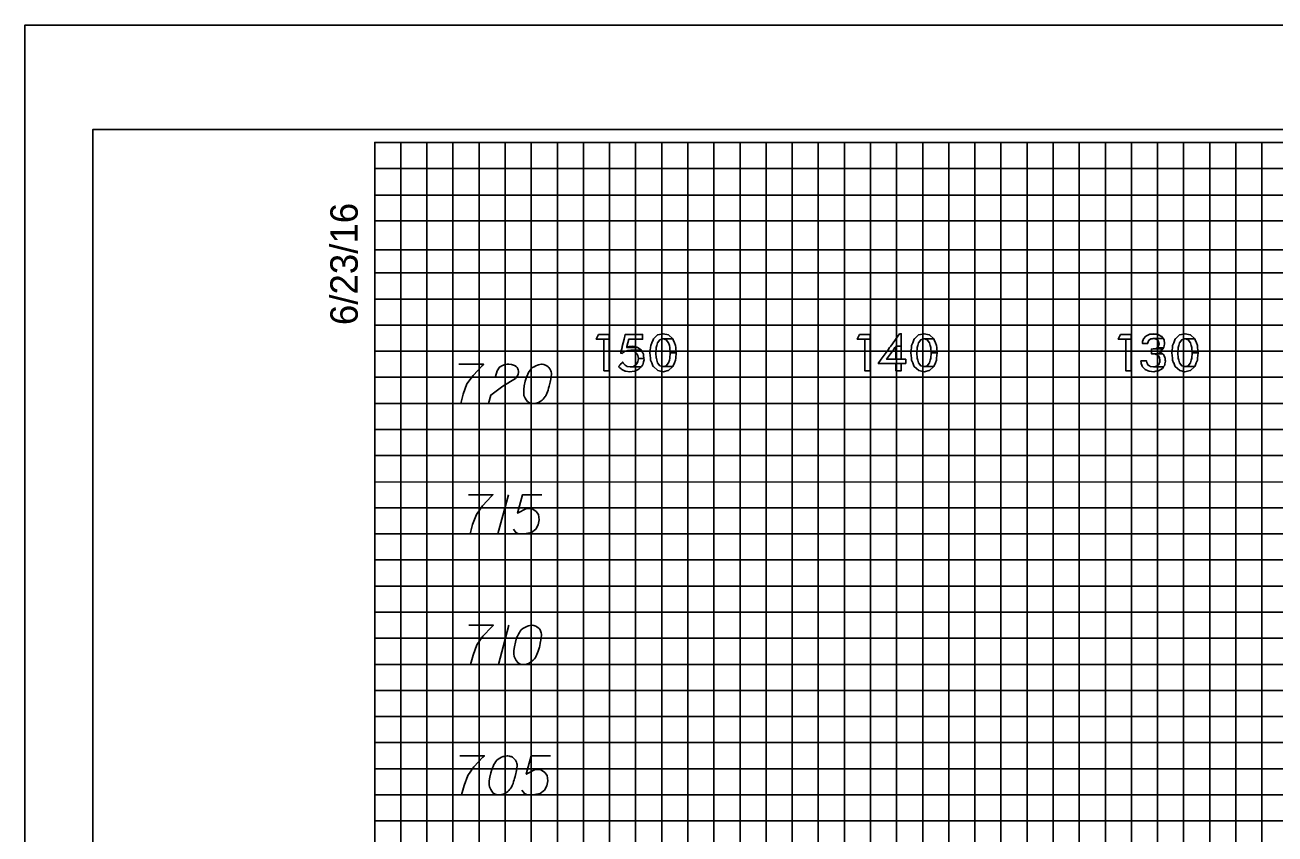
# Model space of a CAD drawing. Extents: x -13 to 323, y -5 to 1431.
# Drawn here: x -13.4 to 34.5, y 623.5 to 654.5 of the extents above; entities that cross this region are included whole.
import ezdxf

# ---------------------------------------------------------------- set-up
doc = ezdxf.new("R2010")
doc.units = 0
for name, color, linetype in [('Prop XS Elevation Labels', 7, 'Continuous'), ('Prop XS Offset Labels', 7, 'Continuous'), ('Sheet Cross Section CELL', 7, 'Continuous'), ('Sheet Cross Section Grid Major CELL', 7, 'Continuous'), ('Sheet Cross Section Grid Middle CELL', 7, 'Continuous'), ('Sheet Cross Section Grid Minor 1 CELL', 7, 'Continuous'), ('Sheet Cross Section Grid Minor 2 CELL', 7, 'Continuous'), ('Sheet Cutting Line CELL', 7, 'Continuous'), ('Sheet DOT Grid CELL', 7, 'Continuous'), ('Sheet Plot Border Inside CELL', 7, 'Continuous'), ('Sheet Plot Border Outside CELL', 7, 'Continuous')]:
    doc.layers.add(name, color=color, linetype=linetype)

msp = doc.modelspace()

# ---------------------------------------------------------------- linework, layer by layer
at = {"layer": 'Prop XS Elevation Labels'}
for p, q in [((5.124, 636.5), (4.723, 635)), ((5.142, 631.5), (4.74, 630))]:
    msp.add_line(p, q, dxfattribs=at)
for points in [[(3.228, 641.5), (4.173, 641.5), (4.114, 641.441), (3.772, 641.075), (3.535, 640.744), (3.394, 640.354), (3.299, 640)], [(4.634, 641.028), (4.693, 641.252), (4.787, 641.394), (4.894, 641.453), (5, 641.488), (5.083, 641.5), (5.142, 641.5), (5.248, 641.488), (5.319, 641.465), (5.354, 641.453), (5.425, 641.417), (5.461, 641.37), (5.484, 641.323), (5.496, 641.287), (5.508, 641.24), (5.508, 641.181), (5.496, 641.122), (5.484, 641.087), (5.461, 641.039), (5.425, 640.992), (5.39, 640.957), (4.906, 640.661), (4.445, 640.319), (4.362, 640), (5.437, 640)], [(6.417, 641.5), (6.394, 641.5), (6.323, 641.488), (6.276, 641.476), (6.24, 641.465), (6.181, 641.441), (6.11, 641.406), (6.051, 641.37), (5.992, 641.323), (5.957, 641.276), (5.921, 641.217), (5.886, 641.158), (5.85, 641.087), (5.827, 641.039), (5.803, 640.969), (5.768, 640.85), (5.732, 640.673), (5.709, 640.531), (5.709, 640.402), (5.721, 640.307), (5.768, 640.201), (5.803, 640.142), (5.862, 640.071), (5.933, 640.024), (5.968, 640.012), (6.039, 640), (6.098, 640), (6.193, 640.012), (6.276, 640.035), (6.335, 640.071), (6.417, 640.13), (6.453, 640.165), (6.5, 640.213), (6.535, 640.26), (6.559, 640.295), (6.583, 640.354), (6.594, 640.378), (6.618, 640.437), (6.642, 640.508), (6.665, 640.579), (6.677, 640.626), (6.689, 640.661), (6.701, 640.709), (6.724, 640.815), (6.736, 640.874), (6.748, 640.933), (6.76, 641.016), (6.772, 641.122), (6.772, 641.158), (6.76, 641.205), (6.748, 641.252), (6.713, 641.323), (6.677, 641.37), (6.642, 641.406), (6.594, 641.441), (6.547, 641.465), (6.512, 641.476), (6.476, 641.488), (6.417, 641.5)], [(3.589, 636.5), (4.533, 636.5), (4.474, 636.441), (4.132, 636.075), (3.896, 635.744), (3.754, 635.354), (3.659, 635)], [(6.411, 636.5), (5.667, 636.5), (5.478, 635.791), (5.821, 635.969), (6.022, 635.969), (6.187, 635.862), (6.282, 635.744), (6.305, 635.543), (6.27, 635.342), (6.175, 635.177), (6.01, 635.047), (5.726, 635), (5.514, 635), (5.408, 635.047), (5.313, 635.177)], [(3.606, 631.5), (4.551, 631.5), (4.492, 631.441), (4.149, 631.075), (3.913, 630.744), (3.772, 630.354), (3.677, 630)], [(6.039, 631.5), (6.016, 631.5), (5.945, 631.488), (5.898, 631.476), (5.862, 631.465), (5.803, 631.441), (5.732, 631.406), (5.673, 631.37), (5.614, 631.323), (5.579, 631.276), (5.543, 631.217), (5.508, 631.158), (5.472, 631.087), (5.449, 631.039), (5.425, 630.969), (5.39, 630.85), (5.354, 630.673), (5.331, 630.531), (5.331, 630.402), (5.343, 630.307), (5.39, 630.201), (5.425, 630.142), (5.484, 630.071), (5.555, 630.024), (5.591, 630.012), (5.661, 630), (5.72, 630), (5.815, 630.012), (5.898, 630.035), (5.957, 630.071), (6.039, 630.13), (6.075, 630.165), (6.122, 630.213), (6.157, 630.26), (6.181, 630.295), (6.205, 630.354), (6.217, 630.378), (6.24, 630.437), (6.264, 630.508), (6.287, 630.579), (6.299, 630.626), (6.311, 630.661), (6.323, 630.709), (6.347, 630.815), (6.358, 630.874), (6.37, 630.933), (6.382, 631.016), (6.394, 631.122), (6.394, 631.158), (6.382, 631.205), (6.37, 631.252), (6.335, 631.323), (6.299, 631.37), (6.264, 631.406), (6.217, 631.441), (6.169, 631.465), (6.134, 631.476), (6.098, 631.488), (6.039, 631.5)], [(3.258, 626.5), (4.203, 626.5), (4.144, 626.441), (3.801, 626.075), (3.565, 625.744), (3.423, 625.354), (3.329, 625)], [(5.1, 626.5), (5.077, 626.5), (5.006, 626.488), (4.959, 626.476), (4.923, 626.465), (4.864, 626.441), (4.793, 626.406), (4.734, 626.37), (4.675, 626.323), (4.64, 626.276), (4.604, 626.217), (4.569, 626.158), (4.534, 626.087), (4.51, 626.039), (4.486, 625.969), (4.451, 625.85), (4.415, 625.673), (4.392, 625.531), (4.392, 625.402), (4.404, 625.307), (4.451, 625.201), (4.486, 625.142), (4.545, 625.071), (4.616, 625.024), (4.652, 625.012), (4.723, 625), (4.781, 625), (4.876, 625.012), (4.959, 625.035), (5.018, 625.071), (5.1, 625.13), (5.136, 625.165), (5.183, 625.213), (5.219, 625.26), (5.242, 625.295), (5.266, 625.354), (5.278, 625.378), (5.301, 625.437), (5.325, 625.508), (5.349, 625.579), (5.36, 625.626), (5.372, 625.661), (5.384, 625.709), (5.408, 625.815), (5.419, 625.874), (5.431, 625.933), (5.443, 626.016), (5.455, 626.122), (5.455, 626.158), (5.443, 626.205), (5.431, 626.252), (5.396, 626.323), (5.36, 626.37), (5.325, 626.406), (5.278, 626.441), (5.23, 626.465), (5.195, 626.476), (5.16, 626.488), (5.1, 626.5)], [(6.742, 626.5), (5.998, 626.5), (5.809, 625.791), (6.152, 625.969), (6.352, 625.969), (6.518, 625.862), (6.612, 625.744), (6.636, 625.543), (6.6, 625.342), (6.506, 625.177), (6.341, 625.047), (6.057, 625), (5.845, 625), (5.738, 625.047), (5.644, 625.177)]]:
    msp.add_lwpolyline(points, dxfattribs=at)
at = {"layer": 'Prop XS Offset Labels'}
for points in [[(8.581, 642.641), (8.492, 642.459), (8.99, 642.459), (8.99, 642.641)], [(8.781, 642.459), (8.781, 641.25), (8.99, 641.25), (8.99, 642.459)], [(9.427, 641.94), (9.424, 641.928), (9.495, 641.928), (9.508, 641.94), (9.524, 641.954), (9.595, 641.997), (9.627, 642.007), (9.697, 642.029), (9.811, 642.035), (10.219, 642.035), (10.211, 642.05), (10.076, 642.145), (9.655, 642.145), (9.658, 642.158), (9.658, 642.158), (9.663, 642.178), (9.738, 642.456), (10.263, 642.456), (10.263, 642.641), (9.6, 642.641), (9.554, 642.456), (9.486, 642.178), (9.481, 642.158), (9.478, 642.145), (9.454, 642.05), (9.451, 642.035), (9.449, 642.029), (9.444, 642.007), (9.441, 641.997), (9.431, 641.954)], [(10.851, 641.255), (11.051, 641.214), (11.245, 641.255), (11.256, 641.257), (11.422, 641.409), (11.047, 641.409), (11.038, 641.411), (11.033, 641.413), (10.928, 641.442), (10.841, 641.555), (10.841, 641.556), (10.841, 641.556), (10.813, 641.657), (10.813, 641.659), (10.793, 641.732), (10.792, 641.736), (10.774, 641.939), (10.774, 641.941), (10.774, 641.943), (10.792, 642.145), (10.812, 642.222), (10.813, 642.224), (10.839, 642.322), (10.84, 642.325), (10.928, 642.44), (11.041, 642.469), (11.045, 642.47), (11.055, 642.473), (11.425, 642.473), (11.262, 642.622), (11.254, 642.624), (11.053, 642.668), (11.053, 642.668), (10.845, 642.624), (10.843, 642.622), (10.681, 642.473), (10.678, 642.47), (10.678, 642.469), (10.665, 642.44), (10.618, 642.325), (10.617, 642.322), (10.577, 642.224), (10.576, 642.222), (10.568, 642.145), (10.547, 641.943), (10.547, 641.941), (10.547, 641.939), (10.567, 641.736), (10.568, 641.732), (10.575, 641.659), (10.575, 641.657), (10.616, 641.556), (10.617, 641.555), (10.663, 641.442), (10.675, 641.413), (10.676, 641.411), (10.679, 641.409), (10.848, 641.257)], [(11.312, 642.145), (11.328, 641.943), (11.555, 641.943), (11.536, 642.145), (11.528, 642.222), (11.527, 642.224), (11.527, 642.224), (11.488, 642.322), (11.488, 642.322), (11.487, 642.325), (11.441, 642.44), (11.44, 642.44), (11.429, 642.469), (11.428, 642.47), (11.425, 642.473), (11.055, 642.473), (11.065, 642.47), (11.068, 642.469), (11.175, 642.44), (11.262, 642.325), (11.265, 642.322), (11.291, 642.224), (11.291, 642.222)], [(18.581, 642.641), (18.492, 642.459), (18.99, 642.459), (18.99, 642.641)], [(18.781, 642.459), (18.781, 641.25), (18.99, 641.25), (18.99, 642.459)], [(19.411, 641.693), (19.297, 641.534), (20.35, 641.534), (20.35, 641.693), (19.618, 641.693), (19.878, 642.059), (19.935, 642.139), (19.977, 642.199), (20.179, 642.199), (20.179, 642.668), (20.114, 642.668), (19.775, 642.199), (19.733, 642.139), (19.675, 642.059)], [(20.851, 641.255), (21.051, 641.214), (21.245, 641.255), (21.256, 641.257), (21.422, 641.409), (21.047, 641.409), (21.038, 641.411), (21.033, 641.413), (20.928, 641.442), (20.841, 641.555), (20.841, 641.556), (20.841, 641.556), (20.813, 641.657), (20.813, 641.659), (20.793, 641.732), (20.792, 641.736), (20.774, 641.939), (20.774, 641.941), (20.774, 641.943), (20.792, 642.145), (20.812, 642.222), (20.813, 642.224), (20.839, 642.322), (20.84, 642.325), (20.928, 642.44), (21.041, 642.469), (21.045, 642.47), (21.055, 642.473), (21.425, 642.473), (21.262, 642.622), (21.254, 642.624), (21.053, 642.668), (21.053, 642.668), (20.845, 642.624), (20.843, 642.622), (20.681, 642.473), (20.678, 642.47), (20.678, 642.469), (20.665, 642.44), (20.618, 642.325), (20.617, 642.322), (20.577, 642.224), (20.576, 642.222), (20.568, 642.145), (20.547, 641.943), (20.547, 641.941), (20.547, 641.939), (20.567, 641.736), (20.567, 641.732), (20.575, 641.659), (20.575, 641.657), (20.616, 641.556), (20.617, 641.555), (20.663, 641.442), (20.675, 641.413), (20.676, 641.411), (20.679, 641.409), (20.848, 641.257)], [(21.312, 642.145), (21.328, 641.943), (21.555, 641.943), (21.536, 642.145), (21.528, 642.222), (21.527, 642.224), (21.527, 642.224), (21.488, 642.322), (21.488, 642.322), (21.487, 642.325), (21.441, 642.44), (21.44, 642.44), (21.429, 642.469), (21.428, 642.47), (21.425, 642.473), (21.055, 642.473), (21.065, 642.47), (21.068, 642.469), (21.175, 642.44), (21.262, 642.325), (21.265, 642.322), (21.291, 642.224), (21.291, 642.222)], [(28.581, 642.641), (28.492, 642.459), (28.99, 642.459), (28.99, 642.641)], [(28.781, 642.459), (28.781, 641.25), (28.99, 641.25), (28.99, 642.459)], [(29.42, 642.315), (29.418, 642.297), (29.626, 642.297), (29.627, 642.315), (29.639, 642.365), (29.64, 642.372), (29.641, 642.373), (29.683, 642.433), (29.688, 642.436), (29.696, 642.44), (29.748, 642.47), (29.785, 642.476), (29.795, 642.478), (29.835, 642.485), (30.217, 642.485), (30.165, 642.561), (30.129, 642.582), (30.128, 642.582), (30.023, 642.644), (29.982, 642.65), (29.69, 642.65), (29.678, 642.644), (29.553, 642.582), (29.536, 642.561), (29.471, 642.485), (29.466, 642.478), (29.465, 642.476), (29.463, 642.47), (29.452, 642.44), (29.45, 642.436), (29.449, 642.433), (29.428, 642.373), (29.427, 642.372), (29.425, 642.365)], [(29.853, 642.668), (29.69, 642.65), (29.982, 642.65)], [(30.007, 642.155), (29.988, 642.131), (30.23, 642.131), (30.246, 642.155), (30.254, 642.201), (30.271, 642.289), (30.272, 642.295), (30.272, 642.297), (30.269, 642.315), (30.26, 642.365), (30.259, 642.372), (30.259, 642.373), (30.259, 642.373), (30.249, 642.433), (30.248, 642.436), (30.248, 642.44), (30.227, 642.47), (30.223, 642.476), (30.222, 642.478), (30.217, 642.485), (29.835, 642.485), (29.901, 642.478), (29.919, 642.476), (29.931, 642.47), (29.986, 642.44), (29.995, 642.436), (29.997, 642.433), (30.04, 642.373), (30.04, 642.372), (30.042, 642.365), (30.051, 642.315), (30.054, 642.297), (30.055, 642.295), (30.056, 642.289), (30.041, 642.201)], [(30.851, 641.255), (31.051, 641.214), (31.245, 641.255), (31.256, 641.257), (31.422, 641.409), (31.047, 641.409), (31.038, 641.411), (31.033, 641.413), (30.928, 641.442), (30.841, 641.555), (30.841, 641.556), (30.841, 641.556), (30.813, 641.657), (30.813, 641.659), (30.793, 641.732), (30.792, 641.736), (30.774, 641.939), (30.774, 641.941), (30.774, 641.943), (30.792, 642.145), (30.812, 642.222), (30.813, 642.224), (30.839, 642.322), (30.84, 642.325), (30.928, 642.44), (31.041, 642.469), (31.045, 642.47), (31.055, 642.473), (31.425, 642.473), (31.262, 642.622), (31.254, 642.624), (31.053, 642.668), (31.053, 642.668), (30.845, 642.624), (30.843, 642.622), (30.681, 642.473), (30.678, 642.47), (30.678, 642.469), (30.665, 642.44), (30.618, 642.325), (30.617, 642.322), (30.577, 642.224), (30.576, 642.222), (30.568, 642.145), (30.547, 641.943), (30.547, 641.941), (30.547, 641.939), (30.567, 641.736), (30.567, 641.732), (30.575, 641.659), (30.575, 641.657), (30.616, 641.556), (30.617, 641.555), (30.663, 641.442), (30.675, 641.413), (30.676, 641.411), (30.679, 641.409), (30.848, 641.257)], [(31.312, 642.145), (31.328, 641.943), (31.555, 641.943), (31.536, 642.145), (31.528, 642.222), (31.527, 642.224), (31.527, 642.224), (31.488, 642.322), (31.488, 642.322), (31.487, 642.325), (31.441, 642.44), (31.44, 642.44), (31.429, 642.469), (31.428, 642.47), (31.425, 642.473), (31.055, 642.473), (31.065, 642.47), (31.068, 642.469), (31.175, 642.44), (31.262, 642.325), (31.265, 642.322), (31.291, 642.224), (31.291, 642.222)], [(9.424, 641.928), (9.482, 641.916), (9.495, 641.928)], [(9.692, 642.158), (9.655, 642.145), (10.076, 642.145), (10.058, 642.158), (9.961, 642.178), (9.75, 642.178)], [(9.888, 642.192), (9.75, 642.178), (9.96, 642.178), (9.888, 642.192)], [(10.083, 641.841), (10.105, 641.721), (10.318, 641.721), (10.307, 641.841), (10.307, 641.841), (10.303, 641.881), (10.284, 641.916), (10.278, 641.928), (10.271, 641.94), (10.263, 641.954), (10.24, 641.997), (10.235, 642.007), (10.223, 642.029), (10.219, 642.035), (9.811, 642.035), (9.838, 642.029), (9.928, 642.007), (9.943, 641.997), (10.003, 641.954), (10.024, 641.94), (10.031, 641.928), (10.038, 641.916), (10.059, 641.881)], [(11.058, 641.411), (11.047, 641.409), (11.422, 641.409), (11.425, 641.411), (11.426, 641.413), (11.438, 641.442), (11.485, 641.555), (11.485, 641.556), (11.527, 641.657), (11.528, 641.659), (11.535, 641.732), (11.535, 641.736), (11.555, 641.939), (11.556, 641.941), (11.555, 641.943), (11.328, 641.943), (11.328, 641.941), (11.328, 641.939), (11.312, 641.736), (11.312, 641.732), (11.292, 641.659), (11.291, 641.657), (11.264, 641.556), (11.263, 641.555), (11.175, 641.442), (11.063, 641.413)], [(19.97, 642.059), (19.97, 641.693), (20.179, 641.693), (20.179, 642.059), (20.179, 642.139), (20.179, 642.199), (19.977, 642.199), (19.973, 642.139)], [(21.058, 641.411), (21.047, 641.409), (21.422, 641.409), (21.425, 641.411), (21.426, 641.413), (21.438, 641.442), (21.485, 641.555), (21.485, 641.556), (21.527, 641.657), (21.528, 641.659), (21.535, 641.732), (21.535, 641.736), (21.555, 641.939), (21.556, 641.941), (21.555, 641.943), (21.328, 641.943), (21.328, 641.941), (21.328, 641.939), (21.312, 641.736), (21.312, 641.732), (21.292, 641.659), (21.291, 641.657), (21.264, 641.556), (21.263, 641.555), (21.175, 641.442), (21.063, 641.413)], [(29.765, 641.956), (29.765, 641.9), (30.194, 641.9), (30.119, 641.956), (30.029, 641.983), (30.095, 642), (30.181, 642.053), (30.2, 642.084), (30.201, 642.085), (30.207, 642.095), (29.915, 642.095), (29.83, 642.085), (29.765, 642.084), (29.765, 642.053), (29.765, 642), (29.765, 641.983)], [(29.925, 641.416), (29.849, 641.401), (30.229, 641.401), (30.239, 641.416), (30.243, 641.423), (30.243, 641.423), (30.275, 641.471), (30.277, 641.479), (30.277, 641.482), (30.283, 641.516), (30.292, 641.562), (30.293, 641.567), (30.303, 641.62), (30.297, 641.662), (30.285, 641.751), (30.283, 641.763), (30.25, 641.826), (30.223, 641.877), (30.222, 641.88), (30.197, 641.898), (30.194, 641.9), (29.81, 641.9), (29.878, 641.898), (29.951, 641.88), (29.963, 641.877), (30.033, 641.826), (30.07, 641.763), (30.077, 641.751), (30.092, 641.662), (30.088, 641.62), (30.083, 641.567), (30.08, 641.562), (30.057, 641.516), (30.039, 641.482), (30.035, 641.479), (30.025, 641.471), (29.957, 641.423)], [(29.988, 642.131), (29.915, 642.095), (30.207, 642.095), (30.23, 642.131)], [(31.058, 641.411), (31.047, 641.409), (31.422, 641.409), (31.425, 641.411), (31.426, 641.413), (31.438, 641.442), (31.485, 641.555), (31.485, 641.556), (31.527, 641.657), (31.528, 641.659), (31.535, 641.732), (31.535, 641.736), (31.555, 641.939), (31.556, 641.941), (31.555, 641.943), (31.328, 641.943), (31.328, 641.941), (31.328, 641.939), (31.312, 641.736), (31.312, 641.732), (31.292, 641.659), (31.291, 641.657), (31.264, 641.556), (31.263, 641.555), (31.175, 641.442), (31.063, 641.413)], [(9.626, 641.233), (9.762, 641.214), (9.959, 641.233), (9.968, 641.237), (10.091, 641.297), (10.091, 641.297), (10.141, 641.321), (10.185, 641.375), (10.204, 641.399), (9.793, 641.399), (9.683, 641.418), (9.682, 641.419), (9.679, 641.42), (9.596, 641.466), (9.586, 641.477), (9.58, 641.483), (9.58, 641.483), (9.529, 641.535), (9.497, 641.585), (9.497, 641.585), (9.451, 641.535), (9.404, 641.483), (9.399, 641.477), (9.39, 641.466), (9.348, 641.42), (9.347, 641.419), (9.348, 641.418), (9.363, 641.399), (9.382, 641.375), (9.445, 641.321), (9.474, 641.297), (9.598, 641.237)], [(9.9, 641.418), (9.793, 641.399), (10.204, 641.399), (10.22, 641.418), (10.221, 641.419), (10.222, 641.42), (10.222, 641.42), (10.259, 641.466), (10.268, 641.477), (10.27, 641.483), (10.284, 641.535), (10.299, 641.59), (10.322, 641.674), (10.318, 641.721), (10.105, 641.721), (10.097, 641.674), (10.082, 641.59), (10.047, 641.535), (10.014, 641.483), (10.004, 641.477), (9.987, 641.466), (9.913, 641.42), (9.905, 641.419)], [(19.97, 641.534), (19.97, 641.25), (20.179, 641.25), (20.179, 641.534)], [(29.677, 641.229), (29.854, 641.214), (29.936, 641.229), (30.042, 641.248), (30.123, 641.297), (30.187, 641.336), (30.228, 641.399), (30.229, 641.401), (29.849, 641.401), (29.72, 641.416), (29.711, 641.423), (29.639, 641.471), (29.628, 641.479), (29.626, 641.482), (29.608, 641.516), (29.584, 641.562), (29.584, 641.567), (29.58, 641.62), (29.58, 641.625), (29.361, 641.625), (29.362, 641.62), (29.369, 641.567), (29.37, 641.562), (29.377, 641.516), (29.391, 641.482), (29.392, 641.479), (29.395, 641.471), (29.415, 641.423), (29.418, 641.416), (29.425, 641.401), (29.426, 641.399), (29.49, 641.336), (29.53, 641.297), (29.635, 641.248)]]:
    msp.add_lwpolyline(points, close=True, dxfattribs=at)
at = {"layer": 'Sheet Cross Section CELL'}
msp.add_lwpolyline([(320, 650), (0, 650), (0, 440), (320, 440)], close=True, dxfattribs=at)
at = {"layer": 'Sheet Cross Section Grid Major CELL'}
for p, q in [((10, 650), (0, 650)), ((10, 440), (10, 650)), ((30, 650), (20, 650)), ((20, 650), (20, 440)), ((30, 440), (30, 650))]:
    msp.add_line(p, q, dxfattribs=at)
msp.add_lwpolyline([(0, 640), (320, 640), (320, 630), (0, 630)], dxfattribs=at)
at = {"layer": 'Sheet Cross Section Grid Middle CELL'}
for points in [[(0, 650), (5, 650), (5, 440)], [(15, 440), (15, 650), (25, 650), (25, 440)], [(0, 645), (275, 645)], [(0, 625), (320, 625), (320, 635), (0, 635)]]:
    msp.add_lwpolyline(points, dxfattribs=at)
at = {"layer": 'Sheet Cross Section Grid Minor 1 CELL'}
for p, q in [((0, 649), (260, 649)), ((260, 647.98), (0, 647.98)), ((0, 647.98), (0, 647)), ((0, 647), (260, 647)), ((260, 645.89), (0, 645.89)), ((0, 645.89), (0, 644)), ((0, 644), (320, 644))]:
    msp.add_line(p, q, dxfattribs=at)
for points in [[(0, 643), (270, 643), (320, 643), (320, 642), (0, 642)], [(0, 641), (320, 641), (320, 639), (0, 639)], [(0, 638), (320, 638), (320, 637), (0, 636.98)], [(0, 636), (320, 636), (320, 634), (0, 634)], [(0, 633), (320, 633), (320, 632), (0, 632)], [(0, 631), (320, 631), (320, 629), (0, 629)], [(0, 628), (320, 628), (320, 627), (0, 627)], [(0, 626), (320, 626), (320, 624), (0, 624)]]:
    msp.add_lwpolyline(points, dxfattribs=at)
at = {"layer": 'Sheet Cross Section Grid Minor 2 CELL'}
for points in [[(0, 440), (1, 440), (1, 650), (2, 650), (2, 440)], [(2, 440), (3, 440), (3, 650), (4, 650), (4, 440)], [(5, 440), (6, 440), (6, 650), (7, 650), (7, 440)], [(7, 440), (8, 440), (8, 650), (9, 650), (9, 440)], [(10, 440), (11, 440), (11, 650), (12, 650), (12, 440)], [(12, 440), (13, 440), (13, 650), (14, 650), (14, 440)], [(15, 440), (16, 440), (16, 650), (17, 650), (17, 440)], [(17, 440), (18, 440), (18, 650), (19, 650), (19, 440)], [(20, 440), (21, 440), (21, 650), (22, 650), (22, 440)], [(22, 440), (23, 440), (23, 650), (24, 650), (24, 440)], [(25, 440), (26, 440), (26, 650), (27, 650), (27, 440)], [(27, 440), (28, 440), (28, 650), (29, 650), (29, 440)], [(30, 440), (31, 440), (31, 650), (32, 650), (32, 440)], [(32, 440), (33, 440), (33, 650), (34, 650), (34, 440)]]:
    msp.add_lwpolyline(points, dxfattribs=at)
at = {"layer": 'Sheet Cutting Line CELL'}
for p, q in [((323.3, 654.5), (-13.4, 654.5)), ((-13.4, 654.5), (-13.4, 435.5))]:
    msp.add_line(p, q, dxfattribs=at)
at = {"layer": 'Sheet DOT Grid CELL'}
for p, q in [((10, 440), (10, 650)), ((20, 440), (20, 650)), ((30, 440), (30, 650)), ((0, 640), (320, 640)), ((0, 630), (320, 630))]:
    msp.add_line(p, q, dxfattribs=at)
at = {"layer": 'Sheet Plot Border Inside CELL'}
msp.add_lwpolyline([(-10.8, 439.5), (322.4, 439.5), (322.4, 650.5), (-10.8, 650.5)], close=True, dxfattribs=at)
at = {"layer": 'Sheet Plot Border Outside CELL'}
msp.add_lwpolyline([(-13.4, 435.5), (323.3, 435.5), (323.3, 654.5), (-13.4, 654.5)], close=True, dxfattribs=at)

# ---------------------------------------------------------------- texts
at = {"layer": 'Sheet Cross Section CELL'}
msp.add_text('6/23/16', height=1.05, rotation=90, dxfattribs=at).set_placement((-0.65, 643))

doc.saveas('drawing.dxf')
